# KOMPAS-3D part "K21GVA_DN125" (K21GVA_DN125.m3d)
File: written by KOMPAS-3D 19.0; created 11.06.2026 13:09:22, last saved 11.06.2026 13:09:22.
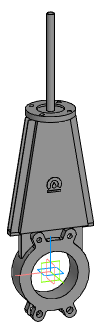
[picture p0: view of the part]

Document properties: Автор: Энергия; Полное имя файла: Z:\3.Личные\kachalov\001_3d для проектировщиков\2.5 Тип_K21GVA. Задвижка\_stp\_stp_K21GVA_DN50-DN1000_с фланцем\K21GVA_DN125.m3d

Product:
- Part/product: K21GVA_DN125

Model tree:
1. Операция без истории:1  (labels: K21GVA_DN125)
